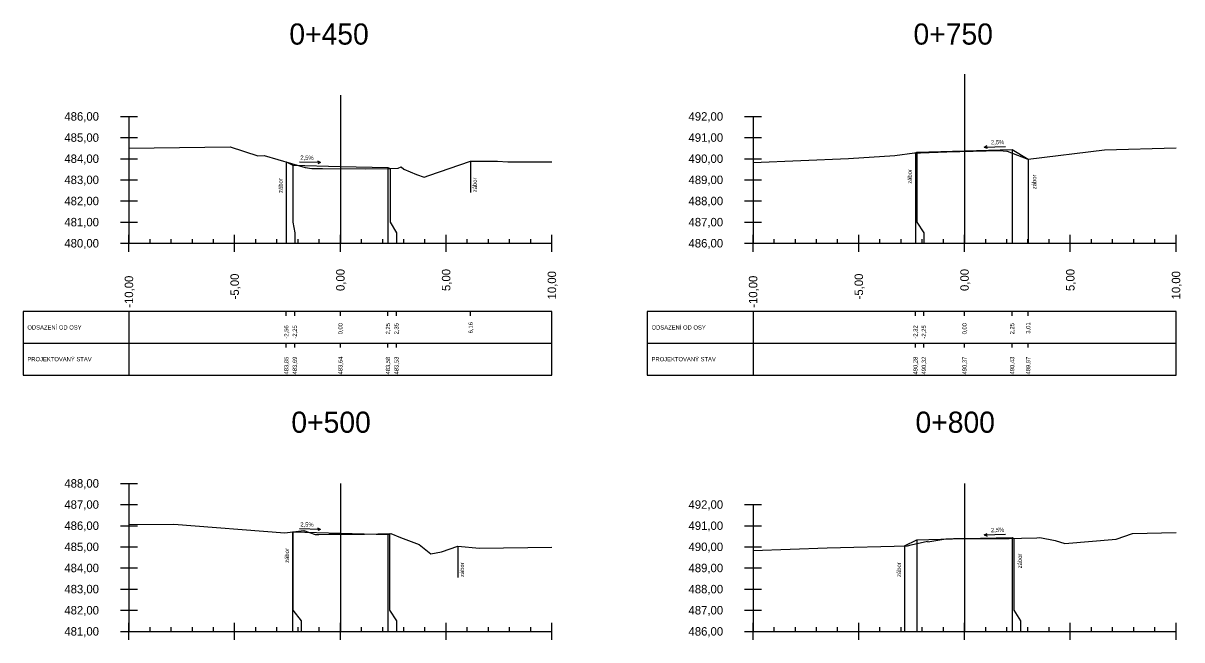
# Model space of a CAD drawing. Extents: x -631407 to -631215, y -1089700 to -1088598.
# Drawn here: x -631373.7 to -631319, y -1089059.3 to -1089030.1 of the extents above; entities that cross this region are included whole.
import ezdxf

# ---------------------------------------------------------------- set-up
doc = ezdxf.new("R2010")
doc.units = 0
for name, color, linetype in [('59', 7, 'Continuous'), ('NIVELETA_VYSKY', 7, 'Continuous'), ('REZ_BODY', 7, 'Continuous'), ('REZ_ODSTUPY', 7, 'Continuous'), ('REZ_POPIS', 7, 'Continuous'), ('REZ_RAMY', 7, 'Continuous'), ('REZ_STANICENI', 7, 'Continuous'), ('REZ_SVISLE', 7, 'Continuous'), ('REZ_TENKA', 7, 'Continuous'), ('REZ_TLUSTA', 7, 'Continuous'), ('TABULKA_POPIS', 7, 'Continuous'), ('TEREN', 7, 'Continuous'), ('zábor', 7, 'Continuous')]:
    doc.layers.add(name, color=color, linetype=linetype)

msp = doc.modelspace()

# ---------------------------------------------------------------- linework, layer by layer
at = {"layer": '59'}
for p, q in [((-631369.144, -1089034.546), (-631368.344, -1089034.546)), ((-631368.744, -1089034.546), (-631368.744, -1089040.546)), ((-631339.63, -1089034.546), (-631338.83, -1089034.546)), ((-631339.23, -1089034.546), (-631339.23, -1089040.546)), ((-631369.144, -1089035.546), (-631368.344, -1089035.546)), ((-631339.63, -1089035.546), (-631338.83, -1089035.546)), ((-631369.144, -1089036.546), (-631368.344, -1089036.546)), ((-631339.63, -1089036.546), (-631338.83, -1089036.546)), ((-631369.144, -1089037.546), (-631368.344, -1089037.546)), ((-631339.63, -1089037.546), (-631338.83, -1089037.546)), ((-631369.144, -1089038.546), (-631368.344, -1089038.546)), ((-631339.63, -1089038.546), (-631338.83, -1089038.546)), ((-631369.144, -1089039.546), (-631368.344, -1089039.546)), ((-631339.63, -1089039.546), (-631338.83, -1089039.546)), ((-631369.144, -1089040.546), (-631368.344, -1089040.546)), ((-631339.63, -1089040.546), (-631338.83, -1089040.546)), ((-631369.144, -1089051.907), (-631368.344, -1089051.907)), ((-631368.744, -1089051.907), (-631368.744, -1089058.907)), ((-631369.144, -1089052.907), (-631368.344, -1089052.907)), ((-631339.63, -1089052.907), (-631338.83, -1089052.907)), ((-631339.23, -1089052.907), (-631339.23, -1089058.907)), ((-631369.144, -1089053.907), (-631368.344, -1089053.907)), ((-631339.63, -1089053.907), (-631338.83, -1089053.907)), ((-631369.144, -1089054.907), (-631368.344, -1089054.907)), ((-631339.63, -1089054.907), (-631338.83, -1089054.907)), ((-631369.144, -1089055.907), (-631368.344, -1089055.907)), ((-631339.63, -1089055.907), (-631338.83, -1089055.907)), ((-631369.144, -1089056.907), (-631368.344, -1089056.907)), ((-631339.63, -1089056.907), (-631338.83, -1089056.907)), ((-631369.144, -1089057.907), (-631368.344, -1089057.907)), ((-631339.63, -1089057.907), (-631338.83, -1089057.907)), ((-631369.144, -1089058.907), (-631368.344, -1089058.907)), ((-631339.63, -1089058.907), (-631338.83, -1089058.907))]:
    msp.add_line(p, q, dxfattribs=at)
at = {"layer": 'REZ_RAMY'}
for p, q in [((-631373.744, -1089043.779), (-631373.744, -1089046.779)), ((-631368.744, -1089043.779), (-631368.744, -1089046.779)), ((-631361.301, -1089043.979), (-631361.301, -1089043.779)), ((-631360.901, -1089043.979), (-631360.901, -1089043.779)), ((-631358.744, -1089043.979), (-631358.744, -1089043.779)), ((-631356.494, -1089043.979), (-631356.494, -1089043.779)), ((-631356.094, -1089043.979), (-631356.094, -1089043.779)), ((-631352.585, -1089043.979), (-631352.585, -1089043.779)), ((-631344.23, -1089043.779), (-631344.23, -1089046.779)), ((-631339.23, -1089043.779), (-631339.23, -1089046.779)), ((-631331.554, -1089043.979), (-631331.554, -1089043.779)), ((-631331.154, -1089043.979), (-631331.154, -1089043.779)), ((-631329.23, -1089043.979), (-631329.23, -1089043.779)), ((-631326.98, -1089043.979), (-631326.98, -1089043.779)), ((-631326.221, -1089043.979), (-631326.221, -1089043.779)), ((-631373.744, -1089045.279), (-631348.744, -1089045.279)), ((-631361.301, -1089045.479), (-631361.301, -1089045.279)), ((-631360.901, -1089045.479), (-631360.901, -1089045.279)), ((-631358.744, -1089045.479), (-631358.744, -1089045.279)), ((-631356.494, -1089045.479), (-631356.494, -1089045.279)), ((-631356.094, -1089045.479), (-631356.094, -1089045.279)), ((-631344.23, -1089045.279), (-631319.23, -1089045.279)), ((-631331.554, -1089045.479), (-631331.554, -1089045.279)), ((-631331.154, -1089045.479), (-631331.154, -1089045.279)), ((-631329.23, -1089045.479), (-631329.23, -1089045.279)), ((-631326.98, -1089045.479), (-631326.98, -1089045.279)), ((-631326.221, -1089045.479), (-631326.221, -1089045.279))]:
    msp.add_line(p, q, dxfattribs=at)
for points in [[(-631373.744, -1089043.779), (-631373.744, -1089046.779), (-631348.744, -1089046.779), (-631348.744, -1089043.779)], [(-631344.23, -1089043.779), (-631344.23, -1089046.779), (-631319.23, -1089046.779), (-631319.23, -1089043.779)]]:
    msp.add_lwpolyline(points, close=True, dxfattribs=at)
at = {"layer": 'REZ_SVISLE'}
for points in [[(-631329.23, -1089036.174), (-631329.23, -1089039.546), (-631329.23, -1089040.046), (-631329.23, -1089040.546)], [(-631326.98, -1089036.117), (-631326.98, -1089039.546), (-631326.98, -1089040.046), (-631326.98, -1089040.546)], [(-631361.301, -1089036.699), (-631361.301, -1089039.546), (-631361.301, -1089040.046), (-631361.301, -1089040.546)], [(-631331.554, -1089036.267), (-631331.554, -1089039.546), (-631331.554, -1089040.046), (-631331.554, -1089040.546)], [(-631331.48, -1089036.23), (-631331.48, -1089039.546), (-631331.154, -1089040.046), (-631331.154, -1089040.546)], [(-631326.221, -1089036.573), (-631326.221, -1089039.546), (-631326.221, -1089040.046), (-631326.221, -1089040.546)], [(-631360.994, -1089036.853), (-631360.994, -1089039.546), (-631360.901, -1089040.046), (-631360.901, -1089040.546)], [(-631358.744, -1089036.909), (-631358.744, -1089039.546), (-631358.744, -1089040.046), (-631358.744, -1089040.546)], [(-631356.494, -1089036.965), (-631356.494, -1089039.546), (-631356.494, -1089040.046), (-631356.494, -1089040.546)], [(-631356.394, -1089037.015), (-631356.394, -1089039.546), (-631356.094, -1089040.046), (-631356.094, -1089040.546)], [(-631361.003, -1089054.2), (-631361.003, -1089057.907), (-631361.003, -1089058.407), (-631361.003, -1089058.907)], [(-631360.994, -1089054.204), (-631360.994, -1089057.907), (-631360.603, -1089058.407), (-631360.603, -1089058.907)], [(-631358.744, -1089054.261), (-631358.744, -1089057.907), (-631358.744, -1089058.407), (-631358.744, -1089058.907)], [(-631356.42, -1089054.28), (-631356.42, -1089057.907), (-631356.094, -1089058.407), (-631356.094, -1089058.907)], [(-631356.494, -1089054.317), (-631356.494, -1089057.907), (-631356.494, -1089058.407), (-631356.494, -1089058.907)], [(-631331.48, -1089054.574), (-631331.48, -1089057.907), (-631331.48, -1089058.407), (-631331.48, -1089058.907)], [(-631329.23, -1089054.517), (-631329.23, -1089057.907), (-631329.23, -1089058.407), (-631329.23, -1089058.907)], [(-631326.98, -1089054.461), (-631326.98, -1089057.907), (-631326.98, -1089058.407), (-631326.98, -1089058.907)], [(-631326.903, -1089054.507), (-631326.903, -1089057.907), (-631326.58, -1089058.407), (-631326.58, -1089058.907)], [(-631332.068, -1089054.868), (-631332.068, -1089057.907), (-631332.068, -1089058.407), (-631332.068, -1089058.907)]]:
    msp.add_lwpolyline(points, dxfattribs=at)
at = {"layer": 'REZ_TENKA'}
for p, q in [((-631367.744, -1089040.546), (-631367.744, -1089040.346)), ((-631366.744, -1089040.546), (-631366.744, -1089040.346)), ((-631365.744, -1089040.546), (-631365.744, -1089040.346)), ((-631364.744, -1089040.546), (-631364.744, -1089040.346)), ((-631362.744, -1089040.546), (-631362.744, -1089040.346)), ((-631361.744, -1089040.546), (-631361.744, -1089040.346)), ((-631360.744, -1089040.546), (-631360.744, -1089040.346)), ((-631359.744, -1089040.546), (-631359.744, -1089040.346)), ((-631357.744, -1089040.546), (-631357.744, -1089040.346)), ((-631356.744, -1089040.546), (-631356.744, -1089040.346)), ((-631355.744, -1089040.546), (-631355.744, -1089040.346)), ((-631354.744, -1089040.546), (-631354.744, -1089040.346)), ((-631352.744, -1089040.546), (-631352.744, -1089040.346)), ((-631351.744, -1089040.546), (-631351.744, -1089040.346)), ((-631350.744, -1089040.546), (-631350.744, -1089040.346)), ((-631349.744, -1089040.546), (-631349.744, -1089040.346)), ((-631338.23, -1089040.546), (-631338.23, -1089040.346)), ((-631337.23, -1089040.546), (-631337.23, -1089040.346)), ((-631336.23, -1089040.546), (-631336.23, -1089040.346)), ((-631335.23, -1089040.546), (-631335.23, -1089040.346)), ((-631333.23, -1089040.546), (-631333.23, -1089040.346)), ((-631332.23, -1089040.546), (-631332.23, -1089040.346)), ((-631331.23, -1089040.546), (-631331.23, -1089040.346)), ((-631330.23, -1089040.546), (-631330.23, -1089040.346)), ((-631328.23, -1089040.546), (-631328.23, -1089040.346)), ((-631327.23, -1089040.546), (-631327.23, -1089040.346)), ((-631326.23, -1089040.546), (-631326.23, -1089040.346)), ((-631325.23, -1089040.546), (-631325.23, -1089040.346)), ((-631323.23, -1089040.546), (-631323.23, -1089040.346)), ((-631322.23, -1089040.546), (-631322.23, -1089040.346)), ((-631321.23, -1089040.546), (-631321.23, -1089040.346)), ((-631320.23, -1089040.546), (-631320.23, -1089040.346)), ((-631367.744, -1089058.907), (-631367.744, -1089058.707)), ((-631366.744, -1089058.907), (-631366.744, -1089058.707)), ((-631365.744, -1089058.907), (-631365.744, -1089058.707)), ((-631364.744, -1089058.907), (-631364.744, -1089058.707)), ((-631362.744, -1089058.907), (-631362.744, -1089058.707)), ((-631361.744, -1089058.907), (-631361.744, -1089058.707)), ((-631360.744, -1089058.907), (-631360.744, -1089058.707)), ((-631359.744, -1089058.907), (-631359.744, -1089058.707)), ((-631357.744, -1089058.907), (-631357.744, -1089058.707)), ((-631356.744, -1089058.907), (-631356.744, -1089058.707)), ((-631355.744, -1089058.907), (-631355.744, -1089058.707)), ((-631354.744, -1089058.907), (-631354.744, -1089058.707)), ((-631352.744, -1089058.907), (-631352.744, -1089058.707)), ((-631351.744, -1089058.907), (-631351.744, -1089058.707)), ((-631350.744, -1089058.907), (-631350.744, -1089058.707)), ((-631349.744, -1089058.907), (-631349.744, -1089058.707)), ((-631338.23, -1089058.907), (-631338.23, -1089058.707)), ((-631337.23, -1089058.907), (-631337.23, -1089058.707)), ((-631336.23, -1089058.907), (-631336.23, -1089058.707)), ((-631335.23, -1089058.907), (-631335.23, -1089058.707)), ((-631333.23, -1089058.907), (-631333.23, -1089058.707)), ((-631332.23, -1089058.907), (-631332.23, -1089058.707)), ((-631331.23, -1089058.907), (-631331.23, -1089058.707)), ((-631330.23, -1089058.907), (-631330.23, -1089058.707)), ((-631328.23, -1089058.907), (-631328.23, -1089058.707)), ((-631327.23, -1089058.907), (-631327.23, -1089058.707)), ((-631326.23, -1089058.907), (-631326.23, -1089058.707)), ((-631325.23, -1089058.907), (-631325.23, -1089058.707)), ((-631323.23, -1089058.907), (-631323.23, -1089058.707)), ((-631322.23, -1089058.907), (-631322.23, -1089058.707)), ((-631321.23, -1089058.907), (-631321.23, -1089058.707)), ((-631320.23, -1089058.907), (-631320.23, -1089058.707))]:
    msp.add_line(p, q, dxfattribs=at)
at = {"layer": 'REZ_TLUSTA'}
for p, q in [((-631329.23, -1089032.546), (-631329.23, -1089040.546)), ((-631358.744, -1089033.546), (-631358.744, -1089040.546)), ((-631368.744, -1089040.946), (-631368.744, -1089040.146)), ((-631368.744, -1089040.546), (-631348.744, -1089040.546)), ((-631363.744, -1089040.946), (-631363.744, -1089040.146)), ((-631358.744, -1089040.946), (-631358.744, -1089040.146)), ((-631353.744, -1089040.946), (-631353.744, -1089040.146)), ((-631348.744, -1089040.946), (-631348.744, -1089040.146)), ((-631339.23, -1089040.946), (-631339.23, -1089040.146)), ((-631339.23, -1089040.546), (-631319.23, -1089040.546)), ((-631334.23, -1089040.946), (-631334.23, -1089040.146)), ((-631329.23, -1089040.946), (-631329.23, -1089040.146)), ((-631324.23, -1089040.946), (-631324.23, -1089040.146)), ((-631319.23, -1089040.946), (-631319.23, -1089040.146)), ((-631358.744, -1089051.907), (-631358.744, -1089058.907)), ((-631329.23, -1089051.907), (-631329.23, -1089058.907)), ((-631368.744, -1089059.307), (-631368.744, -1089058.507)), ((-631363.744, -1089059.307), (-631363.744, -1089058.507)), ((-631358.744, -1089059.307), (-631358.744, -1089058.507)), ((-631353.744, -1089059.307), (-631353.744, -1089058.507)), ((-631348.744, -1089059.307), (-631348.744, -1089058.507)), ((-631339.23, -1089059.307), (-631339.23, -1089058.507)), ((-631334.23, -1089059.307), (-631334.23, -1089058.507)), ((-631329.23, -1089059.307), (-631329.23, -1089058.507)), ((-631324.23, -1089059.307), (-631324.23, -1089058.507)), ((-631319.23, -1089059.307), (-631319.23, -1089058.507)), ((-631368.744, -1089058.907), (-631348.744, -1089058.907)), ((-631339.23, -1089058.907), (-631319.23, -1089058.907))]:
    msp.add_line(p, q, dxfattribs=at)
at = {"layer": 'TEREN'}
for points in [[(-631368.744, -1089036.049), (-631363.955, -1089035.985), (-631362.647, -1089036.413), (-631362.349, -1089036.387), (-631360.417, -1089036.962), (-631360.092, -1089037.006), (-631359.594, -1089037.006), (-631357.579, -1089037.027), (-631356.401, -1089037.015), (-631356.019, -1089036.992), (-631355.874, -1089036.923), (-631355.751, -1089037.046), (-631355.15, -1089037.29), (-631354.779, -1089037.418), (-631354.562, -1089037.344), (-631352.585, -1089036.668), (-631351.316, -1089036.66), (-631350.826, -1089036.701), (-631348.744, -1089036.689)], [(-631339.23, -1089036.727), (-631334.72, -1089036.533), (-631332.526, -1089036.399), (-631331.592, -1089036.265), (-631331.317, -1089036.276), (-631330.063, -1089036.22), (-631327.573, -1089036.165), (-631327.224, -1089036.195), (-631327.209, -1089036.195), (-631326.234, -1089036.573), (-631326.228, -1089036.575), (-631326.217, -1089036.572), (-631322.605, -1089036.121), (-631319.23, -1089036.037)], [(-631331.554, -1089036.267), (-631331.48, -1089036.23), (-631329.23, -1089036.174), (-631326.98, -1089036.117), (-631326.221, -1089036.573)], [(-631361.301, -1089036.699), (-631360.994, -1089036.853), (-631358.744, -1089036.909), (-631356.494, -1089036.965), (-631356.394, -1089037.015)], [(-631368.744, -1089053.844), (-631366.62, -1089053.837), (-631361.366, -1089054.241), (-631360.477, -1089054.14), (-631359.943, -1089054.33), (-631359.767, -1089054.317), (-631359.268, -1089054.303), (-631357.607, -1089054.316), (-631356.36, -1089054.278), (-631355.906, -1089054.47), (-631355.015, -1089054.795), (-631354.461, -1089055.239), (-631353.963, -1089055.137), (-631353.187, -1089054.873), (-631352.163, -1089054.963), (-631348.744, -1089054.92)], [(-631361.003, -1089054.2), (-631360.994, -1089054.204), (-631358.744, -1089054.261), (-631356.494, -1089054.317), (-631356.42, -1089054.28)], [(-631339.23, -1089055.083), (-631335.722, -1089054.957), (-631331.923, -1089054.864), (-631331.75, -1089054.82), (-631330.986, -1089054.645), (-631330.964, -1089054.675), (-631330.11, -1089054.523), (-631329.752, -1089054.511), (-631327.119, -1089054.515), (-631326.539, -1089054.494), (-631325.808, -1089054.483), (-631325.674, -1089054.464), (-631324.944, -1089054.612), (-631324.495, -1089054.747), (-631322.061, -1089054.544), (-631321.294, -1089054.278), (-631319.23, -1089054.222)], [(-631332.068, -1089054.868), (-631331.48, -1089054.574), (-631329.23, -1089054.517), (-631326.98, -1089054.461), (-631326.903, -1089054.507)]]:
    msp.add_lwpolyline(points, dxfattribs=at)
at = {"layer": 'zábor'}
for p, q in [((-631328.297, -1089035.994), (-631328.16, -1089035.929)), ((-631328.297, -1089035.994), (-631327.289, -1089035.969)), ((-631328.297, -1089035.994), (-631328.157, -1089036.052)), ((-631359.677, -1089036.729), (-631360.685, -1089036.704)), ((-631359.677, -1089036.729), (-631359.816, -1089036.787)), ((-631359.677, -1089036.729), (-631359.813, -1089036.665)), ((-631352.585, -1089036.668), (-631352.585, -1089038.148)), ((-631359.677, -1089054.081), (-631360.685, -1089054.056)), ((-631359.677, -1089054.081), (-631359.816, -1089054.139)), ((-631359.677, -1089054.081), (-631359.813, -1089054.017)), ((-631328.297, -1089054.338), (-631328.16, -1089054.273)), ((-631328.297, -1089054.338), (-631327.289, -1089054.313)), ((-631328.297, -1089054.338), (-631328.157, -1089054.395)), ((-631353.187, -1089054.873), (-631353.187, -1089056.354))]:
    msp.add_line(p, q, dxfattribs=at)

# ---------------------------------------------------------------- texts
at = {"layer": 'NIVELETA_VYSKY'}
for s, p in [('483,85', (-631361.201, -1089046.755)), ('483,69', (-631360.801, -1089046.755)), ('483,64', (-631358.644, -1089046.755)), ('483,58', (-631356.394, -1089046.755)), ('483,53', (-631355.994, -1089046.755)), ('490,28', (-631331.454, -1089046.755)), ('490,32', (-631331.054, -1089046.755)), ('490,37', (-631329.13, -1089046.755)), ('490,43', (-631326.88, -1089046.755)), ('489,97', (-631326.121, -1089046.755))]:
    msp.add_text(s, height=0.2, rotation=90, dxfattribs=at).set_placement(p)
at = {"layer": 'REZ_BODY'}
for s, p in [('0,00', (-631358.644, -1089044.858)), ('2,25', (-631356.394, -1089044.858)), ('2,35', (-631355.994, -1089044.858)), ('6,16', (-631352.485, -1089044.811)), ('0,00', (-631329.13, -1089044.858)), ('2,25', (-631326.88, -1089044.858)), ('3,01', (-631326.121, -1089044.825)), ('-2,56', (-631361.201, -1089045.057)), ('-2,25', (-631360.801, -1089045.057)), ('-2,32', (-631331.454, -1089045.057)), ('-2,25', (-631331.054, -1089045.057))]:
    msp.add_text(s, height=0.2, rotation=90, dxfattribs=at).set_placement(p)
at = {"layer": 'REZ_ODSTUPY'}
for s, p in [('-10,00', (-631368.544, -1089043.597)), ('-5,00', (-631363.544, -1089043.201)), ('0,00', (-631358.544, -1089042.804)), ('5,00', (-631353.544, -1089042.804)), ('10,00', (-631348.544, -1089043.201)), ('-10,00', (-631339.03, -1089043.597)), ('-5,00', (-631334.03, -1089043.201)), ('0,00', (-631329.03, -1089042.804)), ('5,00', (-631324.03, -1089042.804)), ('10,00', (-631319.03, -1089043.201))]:
    msp.add_text(s, height=0.4, rotation=90, dxfattribs=at).set_placement(p)
at = {"layer": 'REZ_POPIS'}
for s, p in [('486,00', (-631371.796, -1089034.746)), ('492,00', (-631342.282, -1089034.746)), ('485,00', (-631371.796, -1089035.746)), ('491,00', (-631342.282, -1089035.746)), ('484,00', (-631371.796, -1089036.746)), ('490,00', (-631342.282, -1089036.746)), ('483,00', (-631371.796, -1089037.746)), ('489,00', (-631342.282, -1089037.746)), ('482,00', (-631371.796, -1089038.746)), ('488,00', (-631342.282, -1089038.746)), ('481,00', (-631371.796, -1089039.746)), ('487,00', (-631342.282, -1089039.746)), ('480,00', (-631371.796, -1089040.746)), ('486,00', (-631342.282, -1089040.746)), ('488,00', (-631371.796, -1089052.107)), ('487,00', (-631371.796, -1089053.107)), ('492,00', (-631342.282, -1089053.107)), ('486,00', (-631371.796, -1089054.107)), ('491,00', (-631342.282, -1089054.107)), ('485,00', (-631371.796, -1089055.107)), ('490,00', (-631342.282, -1089055.107)), ('484,00', (-631371.796, -1089056.107)), ('489,00', (-631342.282, -1089056.107)), ('483,00', (-631371.796, -1089057.107)), ('488,00', (-631342.282, -1089057.107)), ('482,00', (-631371.796, -1089058.107)), ('487,00', (-631342.282, -1089058.107)), ('481,00', (-631371.796, -1089059.107)), ('486,00', (-631342.282, -1089059.107))]:
    msp.add_text(s, height=0.4, dxfattribs=at).set_placement(p)
at = {"layer": 'REZ_STANICENI'}
for s, p in [('0+450', (-631361.158, -1089031.149)), ('0+750', (-631331.644, -1089031.149)), ('0+500', (-631361.063, -1089049.511)), ('0+800', (-631331.549, -1089049.511))]:
    msp.add_text(s, height=1, dxfattribs=at).set_placement(p)
at = {"layer": 'TABULKA_POPIS'}
for s, p in [('ODSAZENÍ OD OSY', (-631373.544, -1089044.629)), ('ODSAZENÍ OD OSY', (-631344.03, -1089044.629)), ('PROJEKTOVANÝ STAV', (-631373.544, -1089046.129)), ('PROJEKTOVANÝ STAV', (-631344.03, -1089046.129))]:
    msp.add_text(s, height=0.2, dxfattribs=at).set_placement(p)
at = {"layer": 'zábor'}
for s, rotation, p in [('2,5%', 1.4321, (-631327.98, -1089035.873)), ('2,5%', 358.5679, (-631360.641, -1089036.592)), ('zábor', 90, (-631331.724, -1089037.73)), ('zábor', 90, (-631361.471, -1089038.163)), ('zábor', 90, (-631352.292, -1089038.131)), ('zábor', 90, (-631325.838, -1089037.987)), ('2,5%', 358.5679, (-631360.641, -1089053.944)), ('2,5%', 1.4321, (-631327.98, -1089054.217)), ('zábor', 90, (-631361.173, -1089055.663)), ('zábor', 90, (-631326.52, -1089055.922)), ('zábor', 90, (-631352.894, -1089056.337)), ('zábor', 90, (-631332.238, -1089056.331))]:
    msp.add_text(s, height=0.2, rotation=rotation, dxfattribs=at).set_placement(p)

doc.saveas('drawing.dxf')
